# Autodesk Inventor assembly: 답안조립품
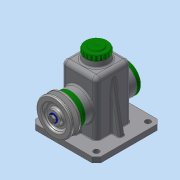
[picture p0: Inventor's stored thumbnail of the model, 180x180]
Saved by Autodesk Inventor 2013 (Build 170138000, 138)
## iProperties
Created: 2018-10
Part Number: 답안조립품
Document SubType Name: Assembly
Designer: Administrator
Author: Administrator
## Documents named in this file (14)
- C:\Users\Administrator\Desktop\481013V1012\답안조립품.iam
- C:\Users\Administrator\Desktop\481013V1012\본체.ipt
- C:\Users\Administrator\Desktop\481013V1012\V-벨트풀리.ipt
- C:\Users\Administrator\Desktop\481013V1012\뒤커버.ipt
- C:\Users\Administrator\Desktop\481013V1012\멈춤링 15 x 1.ipt
- C:\Users\Administrator\Desktop\481013V1012\베어링 15 x 35 x 11.ipt
- C:\Users\Administrator\Desktop\481013V1012\볼트 M4 x 10.ipt
- C:\Users\Administrator\Desktop\481013V1012\볼트 M6 x 12.ipt
- C:\Users\Administrator\Desktop\481013V1012\상부캡.ipt
- C:\Users\Administrator\Desktop\481013V1012\앞커버.ipt
- C:\Users\Administrator\Desktop\481013V1012\오일실 15 25 7.ipt
- C:\Users\Administrator\Desktop\481013V1012\와셔.ipt
- C:\Users\Administrator\Desktop\481013V1012\축.ipt
- C:\Users\Administrator\Desktop\481013V1012\키 5 x 5 x 14.ipt
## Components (1 placed, 1 different names)
1. V-벨트풀리:1
